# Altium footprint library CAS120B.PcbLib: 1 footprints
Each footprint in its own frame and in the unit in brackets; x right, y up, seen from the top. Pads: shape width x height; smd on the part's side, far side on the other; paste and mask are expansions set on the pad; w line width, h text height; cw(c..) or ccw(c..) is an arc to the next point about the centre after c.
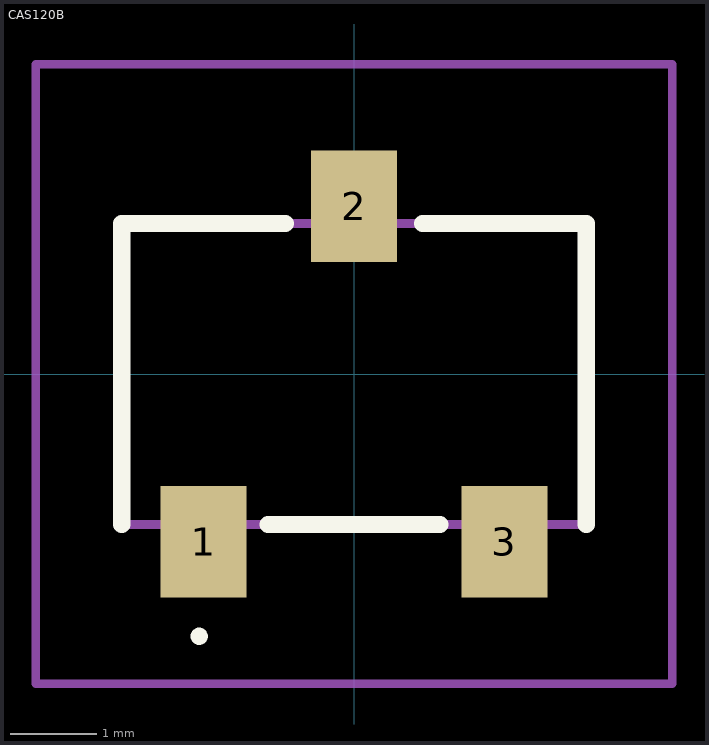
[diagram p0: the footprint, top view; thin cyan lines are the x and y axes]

## CAS120B [mm]
pads (3):
  rect 1x1.3 smd: 1(-1.75,-1.95) 2(0,1.95) 3(1.75,-1.95)
Top Overlay:
  lines w0.1: -1.8,-3.1 cw(c-1.8,-3.05) -1.8,-3 ; -1.8,-3.1 -1.8,-3.1 ; -1.8,-3.1 ccw(c-1.8,-3.05) -1.8,-3 ; -1.8,-3 -1.8,-3
  lines w0.2: -2.7,-1.75 -2.7,1.75 -0.8,1.75 ; -1,-1.75 1,-1.75 ; 0.8,1.75 2.7,1.75 2.7,-1.75
Mechanical 15:
  lines w0.1: -2.7,-1.75 2.7,-1.75 2.7,1.75 -2.7,1.75 -2.7,-1.75
Mechanical 20:
  lines w0.1: -3.7,-3.6 3.7,-3.6 3.7,3.6 -3.7,3.6 -3.7,-3.6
